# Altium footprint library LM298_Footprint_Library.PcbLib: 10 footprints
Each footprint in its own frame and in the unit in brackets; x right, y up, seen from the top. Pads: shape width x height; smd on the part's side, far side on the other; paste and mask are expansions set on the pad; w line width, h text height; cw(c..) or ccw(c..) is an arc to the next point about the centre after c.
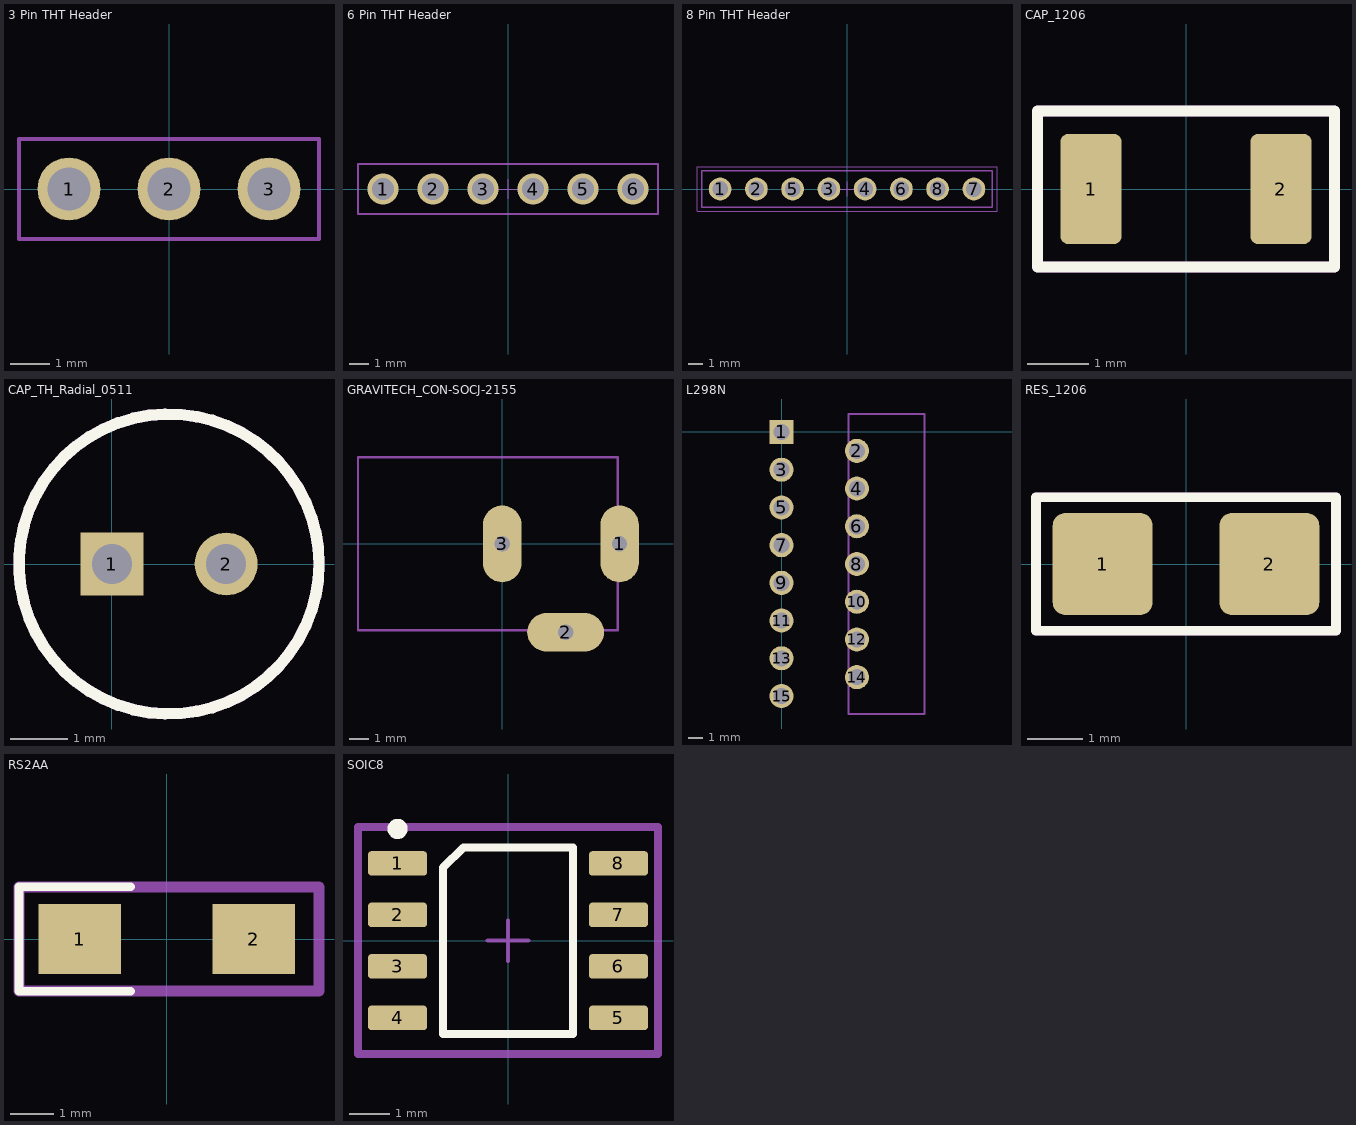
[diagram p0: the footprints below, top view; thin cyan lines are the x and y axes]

## 3 Pin THT Header [mm] "Pin Header, pitch 2.54 mm, THT, Vertical, single row, 3p"
height 8.54
pads (3):
  round 1.6 hole 1.1: 1(-2.54,0) 2(0,0) 3(2.54,0)
Mechanical 13:
  lines w0.1: -3.81,-1.27 3.81,-1.27 3.81,1.27 -3.81,1.27 -3.81,-1.27
  text ".Designator" at -3.2,-0.267 h0.7
Top Component Center:
  lines w0.05: -0.5,0 0.5,0 ; 0,-0.5 0,0.5
3D body "61300311121.stp": height 8.57, standoff -2.97, extent -3.81,-1.27 3.81,1.27

## 6 Pin THT Header [mm] "Pin Header, pitch 2.54 mm, THT, Vertical, single row, 6p"
height 8.54
pads (6):
  round 1.6 hole 1.1: 1(-6.35,0) 2(-3.81,0) 3(-1.27,0) 4(1.27,0) 5(3.81,0) 6(6.35,0)
Mechanical 13:
  lines w0.1: -7.62,-1.27 7.62,-1.27 7.62,1.27 -7.62,1.27 -7.62,-1.27
  text ".Designator" at -3.2,-0.167 h0.7
Top Component Center:
  lines w0.05: -0.5,0 0.5,0 ; 0,-0.5 0,0.5
3D body "61300611121.stp": height 8.57, standoff -2.97, extent -7.62,-1.27 7.62,1.27

## 8 Pin THT Header [mm] "Pin Header, pitch 2.54 mm, THT, Vertical, single row, 8p"
height 8.54
pads (8):
  round 1.6 hole 1.1: 1(-8.89,0) 2(-6.35,0) 3(-1.27,0) 4(1.27,0) 5(-3.81,0) 6(3.81,0) 7(8.89,0) 8(6.35,0)
Top Courtyard:
  lines w0.05: -10.51,-1.545 -10.51,1.545 10.51,1.545 10.51,-1.545 -10.51,-1.545
Mechanical 13:
  lines w0.1: -10.16,-1.27 -10.16,1.27 10.16,1.27 10.16,-1.27 -10.16,-1.27
  text ".Designator" at -3.7,-0.167 h0.7
Top Component Center:
  lines w0.05: -0.5,0 0.5,0 ; 0,-0.5 0,0.5
3D body "61300811121.stp": height 8.57, standoff -2.97, extent -10.16,-1.27 10.16,1.27

## CAP_1206 [mm]
pads (2):
  rrect25% 1x1.8 smd: 1(-1.55,0) 2(1.55,0)
Top Overlay:
  lines w0.175: -2.425,-1.275 -2.425,1.275 2.425,1.275 2.425,-1.275 -2.425,-1.275
Mechanical 13:
  lines w0.175: -2.425,-1.275 -2.425,1.275 2.425,1.275 2.425,-1.275 -2.425,-1.275
  text "'.Designator'" at -5.665,-0.417 h1
3D body "C1206.step": height 0.94, standoff 0, extent -1.6,-0.8 1.6,0.8

## CAP_TH_Radial_0511 [mm]
pads (2):
  rect 1.1x1.1 / inner round 1.1 / far side rect 1.1x1.1 hole 0.7: 1(0,0)
  round 1.1 hole 0.7: 2(2,0)
Top Overlay:
  circle w0.2: c1,0 r2.625
Mechanical 13:
  circle w0.2: c1,0 r2.625
  text ".Designator" at -1.424,-0.302 h0.7
3D body "REA010M2CBK-0511P.stp": height 12.5, standoff -10, extent -1.738,-2.747 3.75,2.747

## GRAVITECH_CON-SOCJ-2155 [mm]
height 11.1
pads (3):
  oval 2x4 hole 0.8 square: 1(6.1,0) 3(0,0)
  oval 4x2 hole 0.8 square: 2(3.3,-4.6)
Mechanical 13:
  lines w0.127: -7.5,-4.5 -7.5,4.5 6,4.5 6,-4.5 -7.5,-4.5
  text ".Designator" at -3.8,-0.167 h0.7
3D body "step_temp.STEP": height 11.1, standoff -4.3, extent -7.385,-4.75 6.715,4.5

## L298N [mm]
pads (15):
  rect 1.62x1.62 hole 1.08: 1(0,0)
  round 1.62 hole 1.08: 2(5.08,-1.27) 3(0,-2.54) 4(5.08,-3.81) 5(0,-5.08) 6(5.08,-6.35) 7(0,-7.62) 8(5.08,-8.89) 9(0,-10.16) 10(5.08,-11.43) 11(0,-12.7) 12(5.08,-13.97) 13(0,-15.24) 14(5.08,-16.51) 15(0,-17.78)
Mechanical 13:
  lines w0.127: 4.5,-18.99 4.5,1.21 9.63,1.21 9.63,-18.99 4.5,-18.99
  text ".Designator" at 6.967,-12.6 h0.7
3D body "l298n.stp": height 20.45, standoff -4.5, extent -0.33,-18.908 9.56,1.092

## RES_1206 [mm]
pads (2):
  rrect25% 1.8x1.84 smd: 1(-1.5,0) 2(1.5,0)
Top Overlay:
  lines w0.175: -2.7,-1.2 2.7,-1.2 2.7,1.2 -2.7,1.2 -2.7,-1.2
Mechanical 13:
  lines w0.175: -2.7,-1.2 2.7,-1.2 2.7,1.2 -2.7,1.2 -2.7,-1.2
  text "'.Designator'" at -5.665,-0.417 h1
3D body "R1206.step": height 0.57, standoff 0.01, extent -1.6,-0.83 1.6,0.83

## RS2AA [mm]
pads (2):
  rect 1.9x1.6 smd: 1(-2,0) 2(2,0)
Top Overlay:
  lines w0.2: -0.833,-1.2 -3.4,-1.2 -3.4,1.2 -0.833,1.2
Mechanical 13:
  lines w0.254: -3.4,-1.2 3.5,-1.2 3.5,1.2 -3.4,1.2 -3.4,-1.2
  text ".Designator" at -2.6,-0.167 h0.7
3D body: height 2.5, standoff 0, extent -2.3,-1 2.3,1

## SOIC8 [mm] "SOIC, 8-Leads, Body 4.91x3.90mm, Pitch 1.27mm, IPC Medium Density"
height 1.75
pads (8):
  rrect25% 1.45x0.6 smd: 1(-2.725,1.905) 2(-2.725,0.635) 3(-2.725,-0.635) 4(-2.725,-1.905) 5(2.725,-1.905) 6(2.725,-0.635) 7(2.725,0.635) 8(2.725,1.905)
Top Overlay:
  circle w0.25: c-2.725,2.755 r0.125
  lines w0.2: -1.6,-2.3 1.6,-2.3 1.6,2.3 -1.1,2.3 -1.6,1.8 -1.6,-2.3
Mechanical 13:
  circle w0.3: c-2.7,1.9 r0.12
  lines w0.2: -3.7,-2.8 3.7,-2.8 3.7,2.8 -3.7,2.8 -3.7,-2.8
  text "'.Designator'" at -6.315,-1.4 h1
Mechanical 15:
  lines w0.05: -3.7,-2.75 -3.7,2.75 3.7,2.75 3.7,-2.75 -3.7,-2.75
  lines w0.1: -0.5,0 0.5,0 ; 0,-0.5 0,0.5
3D body "SOIC-8.step": height 1.75, standoff 0, extent -2.997,-2.5 2.997,2.5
